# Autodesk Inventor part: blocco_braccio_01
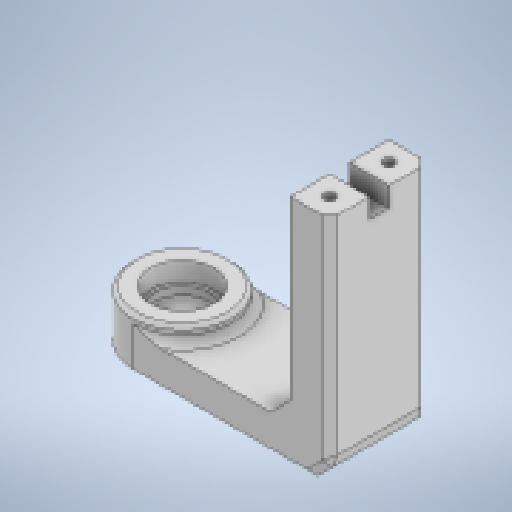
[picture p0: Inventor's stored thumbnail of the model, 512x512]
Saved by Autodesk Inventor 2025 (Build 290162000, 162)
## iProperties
Created: 2025-11
Part Number: blocco_braccio_01
Material: Generico
Document SubType Name: Modeling
Designer: Ryzen5700u
Density: 1 g/cm^3
Appearance: Default
Author: Ryzen5700u
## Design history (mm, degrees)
sketch "Schizzo1" dims "d0" = 25
  geometry: L1 (0, -12.5)-(-50, -12.5); L2 (-50, -12.5)-(-50, 12.5); L3 (-50, 12.5)-(0, 12.5); L4 (0, 12.5)-(0, -12.5); L5 (0, 0)-(-74.753, 0); 2 further points
  constraints: 10 end point, 2 horizontal, 2 parallel, 1 coincident, 1 perpendicular, 4 other
  dimensions: "d3" = 50 distance of L2.end L3.end; "d4" = 25 distance of L1.end L2.end
extrude "Estrusione1" new body sketch "Schizzo1" distance "d1" = 10; taper "d2" = 0 deg
node "Piano di lavoro1"
sketch "Schizzo2"
  geometry: L1 (50, 12.5)-(50, -12.5) reference; L2 (0, 12.5)-(50, 12.5) reference; L3 (50, -12.5)-(40, -12.5); L4 (40, -12.5)-(40, 12.5); L5 (40, 12.5)-(50, 12.5); L6 (50, 12.5)-(50, -12.5); L7 (40, -3)-(50, -3); L8 (50, -3)-(50, 3); L9 (50, 3)-(40, 3); L10 (40, 3)-(40, -3); L11 (0, 0)-(50, 0)
  constraints: 18 end point, 4 parallel, 3 perpendicular, 3 point on line, 2 horizontal, 1 midpoint, 1 other
  dimensions: "d5" = 10 distance of L4.end L5.end; "d6" = 6 distance of L8.end L7.end
extrude "Estrusione2" join sketch "Schizzo2" stored distance "d7" = 6; taper "d8" = 0 deg
node "Piano di lavoro2"
sketch "Schizzo4"
  geometry: C1 r 8 at (0, 0); 1 further point
  constraints: 1 centre point, 1 coincident
  dimensions: "d15" = 16 diameter of C1
extrude "Estrusione4" cut sketch "Schizzo4" distance "d16" = 3; taper "d17" = 0 deg
sketch "Schizzo5"
  geometry: C1 r 12.5 at (0, 0); C2 r 8 at (0, 0) reference; 1 further point
  constraints: 1 centre point, 1 coincident
  dimensions: "d30" = 25 diameter of C1
extrude "Estrusione5" join sketch "Schizzo5" distance "d18" = 4; taper "d19" = 0 deg
fillet "Raccordo2" dims "d20" = 2
sketch "Schizzo7"
  geometry: L1 (24.5, 15)-(-25.21, 15) reference; L2 (-25.21, 10)-(24.5, 10) reference; L3 (0, 25)-(0, 0) reference; L4 (10, 0)-(10, 25) reference; 5 further points
  node "Riferimento3"
  node "Riferimento4"
node "Piano di lavoro3"
extrude "Estrusione6" cut sketch "Schizzo7" stored distance "d21" = 4; taper "d22" = 0 deg
sketch "Schizzo8"
  geometry: L1 (0, 0)-(10, 0) reference; L2 (5, 0)-(5, 10); L3 (0, 10)-(10, 10) reference; L4 (10, 25)-(0, 25) reference; L5 (5, 25)-(5, 15); L6 (10, 15)-(0, 15) reference; 3 further points
  constraints: 6 midpoint, 4 end point
hole "Foro1" sketch "Schizzo8" at (5, 5), (5, 20) diameter "d23" = 2.7; stored, may be unused: countersink angle "d27" = 90 deg, drill point angle "d29" = 118 deg; dims "d24" = 6, "d25" = 5.5, "d26" = 2.9, "d28" = 12
sketch "Schizzo9"
  geometry: C1 r 7 at (0, 0); C2 r 8 at (0, 0) reference; 1 further point
  constraints: 1 centre point, 1 coincident
  dimensions: "d31" = 14 diameter of C1
extrude "Estrusione7" join sketch "Schizzo9" distance "d32" = 2; taper "d33" = 0 deg
chamfer "Smusso2" distance "d34" = 5; stored, may be unused: second distance "d35" = 2, angle "d36" = 45 deg
chamfer "Smusso3" distance "d37" = 2; stored, may be unused: second distance "d38" = 2, angle "d39" = 45 deg
chamfer "Smusso4" distance "d40" = 1; stored, may be unused: second distance "d41" = 2, angle "d42" = 45 deg
node "Solido1"
